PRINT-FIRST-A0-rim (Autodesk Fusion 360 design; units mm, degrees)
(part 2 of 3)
sketch "B Facet 180 Triangle 3" plane through (0, -75, 0) normal (0, -1, 0) x axis (-1, 0, 0)
  line L1 (60.9665, 27.066) -> (-2.067, -27.066)
  line L2 (124, -27.066) -> (60.9665, 27.066)
  line L3 (-2.067, -27.066) -> (124, -27.066)
  line L4 (60.9665, 21.7934) -> (8.7304, -23.066)
  line L5 (113.2026, -23.066) -> (60.9665, 21.7934)
  line L6 (8.7304, -23.066) -> (113.2026, -23.066)
  point P1 (0, 0)
  point P2 (-2.067, -27.066)
  point P3 (60.9665, 27.066)
  point P4 (124, -27.066)
  dimension "d477" distance P1 P2 = 2.067 (= "Linear Dimension-2")
  dimension "d478" distance P1 P2 = 27.066 (= "Linear Dimension-3")
  dimension "d479" distance P1 P3 = 60.9665 (= "Linear Dimension-4")
  dimension "d480" distance P1 P3 = 27.066 (= "Linear Dimension-5")
  dimension "d481" distance P1 P4 = 124 (= "Linear Dimension-6")
  dimension "d482" distance P1 P4 = 27.066 (= "Linear Dimension-7")
  dimension "d483" = 4 (= "memberWidth / 2")
extrude "Extrude14" cut sketch "B Facet 180 Triangle 3" profile of L5 L6 L4 against normal blind 4.7 (magnitude of "-( wall + 0.2 mm )")
sketch "B Facet 180 Triangle 4" plane through (0, -75, 0) normal (0, -1, 0) x axis (-1, 0, 0)
  line L1 (124, -27.066) -> (60.9665, 27.066)
  line L2 (124, 27.066) -> (124, -27.066)
  line L3 (60.9665, 27.066) -> (124, 27.066)
  line L4 (120, -18.3583) -> (71.7639, 23.066)
  line L5 (120, 23.066) -> (120, -18.3583)
  line L6 (71.7639, 23.066) -> (120, 23.066)
  point P1 (0, 0)
  point P2 (60.9665, 27.066)
  point P3 (124, -27.066)
  point P4 (124, 27.066)
  dimension "d486" distance P1 P2 = 60.9665 (= "Linear Dimension-2")
  dimension "d487" distance P1 P2 = 27.066 (= "Linear Dimension-3")
  dimension "d488" distance P1 P3 = 124 (= "Linear Dimension-4")
  dimension "d489" distance P1 P3 = 27.066 (= "Linear Dimension-5")
  dimension "d490" distance P1 P4 = 124 (= "Linear Dimension-6")
  dimension "d491" distance P1 P4 = 27.066 (= "Linear Dimension-7")
  dimension "d492" = -4 (= "-memberWidth / 2")
extrude "Extrude15" cut sketch "B Facet 180 Triangle 4" profile of L5 L6 L4 against normal blind 4.7 (magnitude of "-( wall + 0.2 mm )")
fillet "Fillet5" radius 1.5 (= "apertureRadius")
work_plane "WorkPlane11" RotateAngle 135 ExtraOffset 0
work_plane "WorkPlane12" AlongDistance 75 (= "bodyWidth / 2") ExtraOffset 0
sketch "B Facet 225 Triangle 1" plane through (0, -53.033, -53.033) normal (0, -0.7071, -0.7071) x axis (1, 0, 0)
  line L1 (23.9949, -27.066) -> (62.2721, 27.066)
  line L2 (0.1814, 27.066) -> (23.9949, -27.066)
  line L3 (62.2721, 27.066) -> (0.1814, 27.066)
  line L4 (24.81, -18.9852) -> (54.5447, 23.066)
  line L5 (6.311, 23.066) -> (24.81, -18.9852)
  line L6 (54.5447, 23.066) -> (6.311, 23.066)
  point P1 (0, 0)
  point P2 (62.2721, 27.066)
  point P3 (23.9949, -27.066)
  point P4 (0.1814, 27.066)
  dimension "d501" distance P1 P2 = 62.2721 (= "Linear Dimension-2")
  dimension "d502" distance P1 P2 = 27.066 (= "Linear Dimension-3")
  dimension "d503" distance P1 P3 = 23.9949 (= "Linear Dimension-4")
  dimension "d504" distance P1 P3 = 27.066 (= "Linear Dimension-5")
  dimension "d505" distance P1 P4 = 0.1814 (= "Linear Dimension-6")
  dimension "d506" distance P1 P4 = 27.066 (= "Linear Dimension-7")
  dimension "d507" = 4 (= "memberWidth / 2")
extrude "Extrude16" cut sketch "B Facet 225 Triangle 1" profile of L5 L6 L4 against normal blind 4.7 (magnitude of "-( wall + 0.2 mm )")
sketch "B Facet 225 Triangle 2" plane through (0, -53.033, -53.033) normal (0, -0.7071, -0.7071) x axis (1, 0, 0)
  line L1 (0.1814, 27.066) -> (23.9949, -27.066)
  line L2 (-74.6684, -27.066) -> (0.1814, 27.066)
  line L3 (23.9949, -27.066) -> (-74.6684, -27.066)
  line L4 (-1.4863, 20.9235) -> (17.8653, -23.066)
  line L5 (-62.3117, -23.066) -> (-1.4863, 20.9235)
  line L6 (17.8653, -23.066) -> (-62.3117, -23.066)
  point P1 (0, 0)
  point P2 (23.9949, -27.066)
  point P3 (0.1814, 27.066)
  point P4 (-74.6684, -27.066)
  dimension "d510" distance P1 P2 = 23.9949 (= "Linear Dimension-2")
  dimension "d511" distance P1 P2 = 27.066 (= "Linear Dimension-3")
  dimension "d512" distance P1 P3 = 0.1814 (= "Linear Dimension-4")
  dimension "d513" distance P1 P3 = 27.066 (= "Linear Dimension-5")
  dimension "d514" distance P1 P4 = 74.6684 (= "Linear Dimension-6")
  dimension "d515" distance P1 P4 = 27.066 (= "Linear Dimension-7")
  dimension "d516" = -4 (= "-memberWidth / 2")
extrude "Extrude17" cut sketch "B Facet 225 Triangle 2" profile of L5 L6 L4 against normal blind 4.7 (magnitude of "-( wall + 0.2 mm )")
sketch "B Facet 225 Triangle 3" plane through (0, -53.033, -53.033) normal (0, -0.7071, -0.7071) x axis (1, 0, 0)
  line L1 (-74.6684, -27.066) -> (0.1814, 27.066)
  line L2 (-124, 27.066) -> (-74.6684, -27.066)
  line L3 (0.1814, 27.066) -> (-124, 27.066)
  line L4 (-74.1179, -21.7315) -> (-12.1753, 23.066)
  line L5 (-114.9429, 23.066) -> (-74.1179, -21.7315)
  line L6 (-12.1753, 23.066) -> (-114.9429, 23.066)
  point P1 (0, 0)
  point P2 (0.1814, 27.066)
  point P3 (-74.6684, -27.066)
  point P4 (-124, 27.066)
  dimension "d519" distance P1 P2 = 0.1814 (= "Linear Dimension-2")
  dimension "d520" distance P1 P2 = 27.066 (= "Linear Dimension-3")
  dimension "d521" distance P1 P3 = 74.6684 (= "Linear Dimension-4")
  dimension "d522" distance P1 P3 = 27.066 (= "Linear Dimension-5")
  dimension "d523" distance P1 P4 = 124 (= "Linear Dimension-6")
  dimension "d524" distance P1 P4 = 27.066 (= "Linear Dimension-7")
  dimension "d525" = 4 (= "memberWidth / 2")
extrude "Extrude18" cut sketch "B Facet 225 Triangle 3" profile of L5 L6 L4 against normal blind 4.7 (magnitude of "-( wall + 0.2 mm )")
sketch "B Facet 225 Triangle 4" plane through (0, -53.033, -53.033) normal (0, -0.7071, -0.7071) x axis (1, 0, 0)
  line L1 (-124, 27.066) -> (-74.6684, -27.066)
  line L2 (-124, -27.066) -> (-124, 27.066)
  line L3 (-74.6684, -27.066) -> (-124, -27.066)
  line L4 (-120, 16.7383) -> (-83.7255, -23.066)
  line L5 (-120, -23.066) -> (-120, 16.7383)
  line L6 (-83.7255, -23.066) -> (-120, -23.066)
  point P1 (0, 0)
  point P2 (-74.6684, -27.066)
  point P3 (-124, 27.066)
  point P4 (-124, -27.066)
  dimension "d528" distance P1 P2 = 74.6684 (= "Linear Dimension-2")
  dimension "d529" distance P1 P2 = 27.066 (= "Linear Dimension-3")
  dimension "d530" distance P1 P3 = 124 (= "Linear Dimension-4")
  dimension "d531" distance P1 P3 = 27.066 (= "Linear Dimension-5")
  dimension "d532" distance P1 P4 = 124 (= "Linear Dimension-6")
  dimension "d533" distance P1 P4 = 27.066 (= "Linear Dimension-7")
  dimension "d534" = -4 (= "-memberWidth / 2")
extrude "Extrude19" cut sketch "B Facet 225 Triangle 4" profile of L5 L6 L4 against normal blind 4.7 (magnitude of "-( wall + 0.2 mm )")
fillet "Fillet6" radius 1.5 (= "apertureRadius")
work_plane "WorkPlane13" RotateAngle 180 ExtraOffset 0
work_plane "WorkPlane14" AlongDistance 75 (= "bodyWidth / 2") ExtraOffset 0
sketch "B Facet 270 Triangle 1" plane through (0, 0, -75) normal (0, 0, -1) x axis (-1, 0, 0)
  line L1 (36.9655, 27.066) -> (-17.1665, -27.066)
  line L2 (53.4167, -27.066) -> (36.9655, 27.066)
  line L3 (-17.1665, -27.066) -> (53.4167, -27.066)
  line L4 (35.0777, 19.5214) -> (-7.5097, -23.066)
  line L5 (48.0205, -23.066) -> (35.0777, 19.5214)
  line L6 (-7.5097, -23.066) -> (48.0205, -23.066)
  point P1 (0, 0)
  point P2 (-17.1665, -27.066)
  point P3 (36.9655, 27.066)
  point P4 (53.4167, -27.066)
  dimension "d543" distance P1 P2 = 17.1665 (= "Linear Dimension-2")
  dimension "d544" distance P1 P2 = 27.066 (= "Linear Dimension-3")
  dimension "d545" distance P1 P3 = 36.9655 (= "Linear Dimension-4")
  dimension "d546" distance P1 P3 = 27.066 (= "Linear Dimension-5")
  dimension "d547" distance P1 P4 = 53.4167 (= "Linear Dimension-6")
  dimension "d548" distance P1 P4 = 27.066 (= "Linear Dimension-7")
  dimension "d549" = 4 (= "memberWidth / 2")
extrude "Extrude20" cut sketch "B Facet 270 Triangle 1" profile of L5 L6 L4 against normal blind 4.7 (magnitude of "-( wall + 0.2 mm )")
sketch "B Facet 270 Triangle 2" plane through (0, 0, -75) normal (0, 0, -1) x axis (-1, 0, 0)
  line L1 (53.4167, -27.066) -> (36.9655, 27.066)
  line L2 (124, 27.066) -> (53.4167, -27.066)
  line L3 (36.9655, 27.066) -> (124, 27.066)
  line L4 (55.5648, -20.3777) -> (42.3618, 23.066)
  line L5 (112.2115, 23.066) -> (55.5648, -20.3777)
  line L6 (42.3618, 23.066) -> (112.2115, 23.066)
  point P1 (0, 0)
  point P2 (36.9655, 27.066)
  point P3 (53.4167, -27.066)
  point P4 (124, 27.066)
  dimension "d552" distance P1 P2 = 36.9655 (= "Linear Dimension-2")
  dimension "d553" distance P1 P2 = 27.066 (= "Linear Dimension-3")
  dimension "d554" distance P1 P3 = 53.4167 (= "Linear Dimension-4")
  dimension "d555" distance P1 P3 = 27.066 (= "Linear Dimension-5")
  dimension "d556" distance P1 P4 = 124 (= "Linear Dimension-6")
  dimension "d557" distance P1 P4 = 27.066 (= "Linear Dimension-7")
  dimension "d558" = -4 (= "-memberWidth / 2")
extrude "Extrude21" cut sketch "B Facet 270 Triangle 2" profile of L5 L6 L4 against normal blind 4.7 (magnitude of "-( wall + 0.2 mm )")
sketch "B Facet 270 Triangle 3" plane through (0, 0, -75) normal (0, 0, -1) x axis (-1, 0, 0)
  line L1 (124, 27.066) -> (53.4167, -27.066)
  line L2 (124, -27.066) -> (124, 27.066)
  line L3 (53.4167, -27.066) -> (124, -27.066)
  line L4 (120, 18.9574) -> (65.2053, -23.066)
  line L5 (120, -23.066) -> (120, 18.9574)
  line L6 (65.2053, -23.066) -> (120, -23.066)
  point P1 (0, 0)
  point P2 (53.4167, -27.066)
  point P3 (124, 27.066)
  point P4 (124, -27.066)
  dimension "d561" distance P1 P2 = 53.4167 (= "Linear Dimension-2")
  dimension "d562" distance P1 P2 = 27.066 (= "Linear Dimension-3")
  dimension "d563" distance P1 P3 = 124 (= "Linear Dimension-4")
  dimension "d564" distance P1 P3 = 27.066 (= "Linear Dimension-5")
  dimension "d565" distance P1 P4 = 124 (= "Linear Dimension-6")
  dimension "d566" distance P1 P4 = 27.066 (= "Linear Dimension-7")
  dimension "d567" = 4 (= "memberWidth / 2")
extrude "Extrude22" cut sketch "B Facet 270 Triangle 3" profile of L5 L6 L4 against normal blind 4.7 (magnitude of "-( wall + 0.2 mm )")
fillet "Fillet7" radius 1.5 (= "apertureRadius")
work_plane "WorkPlane15" RotateAngle 225 ExtraOffset 0
work_plane "WorkPlane16" AlongDistance 75 (= "bodyWidth / 2") ExtraOffset 0
sketch "B Facet 315 Triangle 1" plane through (0, 53.033, -53.033) normal (0, 0.7071, -0.7071) x axis (1, 0, 0)
  line L1 (-82.0711, -27.066) -> (-43.7939, 27.066)
  line L2 (-124, 27.066) -> (-82.0711, -27.066)
  line L3 (-43.7939, 27.066) -> (-124, 27.066)
  line L4 (-82.2175, -20.3449) -> (-51.5213, 23.066)
  line L5 (-115.8422, 23.066) -> (-82.2175, -20.3449)
  line L6 (-51.5213, 23.066) -> (-115.8422, 23.066)
  point P1 (0, 0)
  point P2 (-43.7939, 27.066)
  point P3 (-82.0711, -27.066)
  point P4 (-124, 27.066)
  dimension "d576" distance P1 P2 = 43.7939 (= "Linear Dimension-2")
  dimension "d577" distance P1 P2 = 27.066 (= "Linear Dimension-3")
  dimension "d578" distance P1 P3 = 82.0711 (= "Linear Dimension-4")
  dimension "d579" distance P1 P3 = 27.066 (= "Linear Dimension-5")
  dimension "d580" distance P1 P4 = 124 (= "Linear Dimension-6")
  dimension "d581" distance P1 P4 = 27.066 (= "Linear Dimension-7")
  dimension "d582" = 4 (= "memberWidth / 2")
extrude "Extrude23" cut sketch "B Facet 315 Triangle 1" profile of L5 L6 L4 against normal blind 4.7 (magnitude of "-( wall + 0.2 mm )")
sketch "B Facet 315 Triangle 2" plane through (0, 53.033, -53.033) normal (0, 0.7071, -0.7071) x axis (1, 0, 0)
  line L1 (-124, 27.066) -> (-82.0711, -27.066)
  line L2 (-124, -27.066) -> (-124, 27.066)
  line L3 (-82.0711, -27.066) -> (-124, -27.066)
  line L4 (-120, 15.3697) -> (-90.2289, -23.066)
  line L5 (-120, -23.066) -> (-120, 15.3697)
  line L6 (-90.2289, -23.066) -> (-120, -23.066)
  point P1 (0, 0)
  point P2 (-82.0711, -27.066)
  point P3 (-124, 27.066)
  point P4 (-124, -27.066)
  dimension "d585" distance P1 P2 = 82.0711 (= "Linear Dimension-2")
  dimension "d586" distance P1 P2 = 27.066 (= "Linear Dimension-3")
  dimension "d587" distance P1 P3 = 124 (= "Linear Dimension-4")
  dimension "d588" distance P1 P3 = 27.066 (= "Linear Dimension-5")
  dimension "d589" distance P1 P4 = 124 (= "Linear Dimension-6")
  dimension "d590" distance P1 P4 = 27.066 (= "Linear Dimension-7")
  dimension "d591" = -4 (= "-memberWidth / 2")
extrude "Extrude24" cut sketch "B Facet 315 Triangle 2" profile of L5 L6 L4 against normal blind 4.7 (magnitude of "-( wall + 0.2 mm )")
fillet "Fillet8" radius 1.5 (= "apertureRadius")
work_plane "WorkPlane17" AlongDistance 0.5 (= "qFront") ExtraOffset 0
sketch "A Central Carrier sketch" plane through (0.3536, 0.3536, 0) normal (0.7071, 0.7071, 0) x axis (0, 0, 1)
  circle C1 centre (0, 0) radius 26
  dimension "d598" diameter C1 = 52 (= "carrierOD")
extrude "Extrude25" new body sketch "A Central Carrier sketch" along normal blind 18 (= "spokeDepth")
work_plane "WorkPlane18" AlongDistance 0.5 (= "qFront") ExtraOffset 0
sketch "A Spoke 1 Profile" plane through (0.3536, 0.3536, 0) normal (0.7071, 0.7071, 0) x axis (0, 0, 1)
  line L1 (37.3643, -145.3579) -> (-4.7984, -1.4054)
  line L2 (46.9611, -142.547) -> (37.3643, -145.3579)
  line L3 (4.7984, 1.4054) -> (46.9611, -142.547)
  line L4 (-4.7984, -1.4054) -> (4.7984, 1.4054)
  point P1 (0, 0)
  point P2 (-4.7984, -1.4054)
  point P3 (37.3643, -145.3579)
  point P4 (46.9611, -142.547)
  point P5 (4.7984, 1.4054)
  dimension "d603" distance P1 P2 = 4.7984 (= "Linear Dimension-2")
  dimension "d604" distance P1 P2 = 1.4054 (= "Linear Dimension-3")
  dimension "d605" distance P1 P3 = 37.3643 (= "Linear Dimension-4")
  dimension "d606" distance P1 P3 = 145.3579 (= "Linear Dimension-5")
  dimension "d607" distance P1 P4 = 46.9611 (= "Linear Dimension-6")
  dimension "d608" distance P1 P4 = 142.547 (= "Linear Dimension-7")
  dimension "d609" distance P1 P5 = 4.7984 (= "Linear Dimension-8")
  dimension "d610" distance P1 P5 = 1.4054 (= "Linear Dimension-9")
extrude "Extrude26" add sketch "A Spoke 1 Profile" along normal blind 18 (= "spokeDepth")
sketch "A Spoke 2 Profile" plane through (0.3536, 0.3536, 0) normal (0.7071, 0.7071, 0) x axis (0, 0, 1)
  line L1 (126.9012, -80.1317) -> (-2.5272, -4.3143)
  line L2 (131.9557, -71.5031) -> (126.9012, -80.1317)
  line L3 (2.5272, 4.3143) -> (131.9557, -71.5031)
  line L4 (-2.5272, -4.3143) -> (2.5272, 4.3143)
  point P1 (0, 0)
  point P2 (-2.5272, -4.3143)
  point P3 (126.9012, -80.1317)
  point P4 (131.9557, -71.5031)
  point P5 (2.5272, 4.3143)
  dimension "d613" distance P1 P2 = 2.5272 (= "Linear Dimension-2")
  dimension "d614" distance P1 P2 = 4.3143 (= "Linear Dimension-3")
  dimension "d615" distance P1 P3 = 126.9012 (= "Linear Dimension-4")
  dimension "d616" distance P1 P3 = 80.1317 (= "Linear Dimension-5")
  dimension "d617" distance P1 P4 = 131.9557 (= "Linear Dimension-6")
  dimension "d618" distance P1 P4 = 71.5031 (= "Linear Dimension-7")
  dimension "d619" distance P1 P5 = 2.5272 (= "Linear Dimension-8")
  dimension "d620" distance P1 P5 = 4.3143 (= "Linear Dimension-9")
extrude "Extrude27" add sketch "A Spoke 2 Profile" along normal blind 18 (= "spokeDepth")
sketch "A Spoke 3 Profile" plane through (0.3536, 0.3536, 0) normal (0.7071, 0.7071, 0) x axis (0, 0, 1)
  line L1 (131.9557, 71.5031) -> (2.5272, -4.3143)
  line L2 (126.9012, 80.1317) -> (131.9557, 71.5031)
  line L3 (-2.5272, 4.3143) -> (126.9012, 80.1317)
  line L4 (2.5272, -4.3143) -> (-2.5272, 4.3143)
  point P1 (0, 0)
  point P2 (2.5272, -4.3143)
  point P3 (131.9557, 71.5031)
  point P4 (126.9012, 80.1317)
  point P5 (-2.5272, 4.3143)
  dimension "d623" distance P1 P2 = 2.5272 (= "Linear Dimension-2")
  dimension "d624" distance P1 P2 = 4.3143 (= "Linear Dimension-3")
  dimension "d625" distance P1 P3 = 131.9557 (= "Linear Dimension-4")
  dimension "d626" distance P1 P3 = 71.5031 (= "Linear Dimension-5")
  dimension "d627" distance P1 P4 = 126.9012 (= "Linear Dimension-6")
  dimension "d628" distance P1 P4 = 80.1317 (= "Linear Dimension-7")
  dimension "d629" distance P1 P5 = 2.5272 (= "Linear Dimension-8")
  dimension "d630" distance P1 P5 = 4.3143 (= "Linear Dimension-9")
extrude "Extrude28" add sketch "A Spoke 3 Profile" along normal blind 18 (= "spokeDepth")
sketch "A Spoke 4 Profile" plane through (0.3536, 0.3536, 0) normal (0.7071, 0.7071, 0) x axis (0, 0, 1)
  line L1 (46.9611, 142.547) -> (4.7984, -1.4054)
  line L2 (37.3643, 145.3579) -> (46.9611, 142.547)
  line L3 (-4.7984, 1.4054) -> (37.3643, 145.3579)
  line L4 (4.7984, -1.4054) -> (-4.7984, 1.4054)
  point P1 (0, 0)
  point P2 (4.7984, -1.4054)
  point P3 (46.9611, 142.547)
  point P4 (37.3643, 145.3579)
  point P5 (-4.7984, 1.4054)
  dimension "d633" distance P1 P2 = 4.7984 (= "Linear Dimension-2")
  dimension "d634" distance P1 P2 = 1.4054 (= "Linear Dimension-3")
  dimension "d635" distance P1 P3 = 46.9611 (= "Linear Dimension-4")
  dimension "d636" distance P1 P3 = 142.547 (= "Linear Dimension-5")
  dimension "d637" distance P1 P4 = 37.3643 (= "Linear Dimension-6")
  dimension "d638" distance P1 P4 = 145.3579 (= "Linear Dimension-7")
  dimension "d639" distance P1 P5 = 4.7984 (= "Linear Dimension-8")
  dimension "d640" distance P1 P5 = 1.4054 (= "Linear Dimension-9")
extrude "Extrude29" add sketch "A Spoke 4 Profile" along normal blind 18 (= "spokeDepth")
sketch "A Spoke 5 Profile" plane through (0.3536, 0.3536, 0) normal (0.7071, 0.7071, 0) x axis (0, 0, 1)
  line L1 (-37.3643, 145.3579) -> (4.7984, 1.4054)
  line L2 (-46.9611, 142.547) -> (-37.3643, 145.3579)
  line L3 (-4.7984, -1.4054) -> (-46.9611, 142.547)
  line L4 (4.7984, 1.4054) -> (-4.7984, -1.4054)
  point P1 (0, 0)
  point P2 (4.7984, 1.4054)
  point P3 (-37.3643, 145.3579)
  point P4 (-46.9611, 142.547)
  point P5 (-4.7984, -1.4054)
  dimension "d643" distance P1 P2 = 4.7984 (= "Linear Dimension-2")
  dimension "d644" distance P1 P2 = 1.4054 (= "Linear Dimension-3")
  dimension "d645" distance P1 P3 = 37.3643 (= "Linear Dimension-4")
  dimension "d646" distance P1 P3 = 145.3579 (= "Linear Dimension-5")
  dimension "d647" distance P1 P4 = 46.9611 (= "Linear Dimension-6")
  dimension "d648" distance P1 P4 = 142.547 (= "Linear Dimension-7")
  dimension "d649" distance P1 P5 = 4.7984 (= "Linear Dimension-8")
  dimension "d650" distance P1 P5 = 1.4054 (= "Linear Dimension-9")
extrude "Extrude30" add sketch "A Spoke 5 Profile" along normal blind 18 (= "spokeDepth")
sketch "A Spoke 6 Profile" plane through (0.3536, 0.3536, 0) normal (0.7071, 0.7071, 0) x axis (0, 0, 1)
  line L1 (-126.9012, 80.1317) -> (2.5272, 4.3143)
  line L2 (-131.9557, 71.5031) -> (-126.9012, 80.1317)
  line L3 (-2.5272, -4.3143) -> (-131.9557, 71.5031)
  line L4 (2.5272, 4.3143) -> (-2.5272, -4.3143)
  point P1 (0, 0)
  point P2 (2.5272, 4.3143)
  point P3 (-126.9012, 80.1317)
  point P4 (-131.9557, 71.5031)
  point P5 (-2.5272, -4.3143)
  dimension "d653" distance P1 P2 = 2.5272 (= "Linear Dimension-2")
  dimension "d654" distance P1 P2 = 4.3143 (= "Linear Dimension-3")
  dimension "d655" distance P1 P3 = 126.9012 (= "Linear Dimension-4")
  dimension "d656" distance P1 P3 = 80.1317 (= "Linear Dimension-5")
  dimension "d657" distance P1 P4 = 131.9557 (= "Linear Dimension-6")
  dimension "d658" distance P1 P4 = 71.5031 (= "Linear Dimension-7")
  dimension "d659" distance P1 P5 = 2.5272 (= "Linear Dimension-8")
  dimension "d660" distance P1 P5 = 4.3143 (= "Linear Dimension-9")
extrude "Extrude31" add sketch "A Spoke 6 Profile" along normal blind 18 (= "spokeDepth")
sketch "A Spoke 7 Profile" plane through (0.3536, 0.3536, 0) normal (0.7071, 0.7071, 0) x axis (0, 0, 1)
  line L1 (-131.9557, -71.5031) -> (-2.5272, 4.3143)
  line L2 (-126.9012, -80.1317) -> (-131.9557, -71.5031)
  line L3 (2.5272, -4.3143) -> (-126.9012, -80.1317)
  line L4 (-2.5272, 4.3143) -> (2.5272, -4.3143)
  point P1 (0, 0)
  point P2 (-2.5272, 4.3143)
  point P3 (-131.9557, -71.5031)
  point P4 (-126.9012, -80.1317)
  point P5 (2.5272, -4.3143)
  dimension "d663" distance P1 P2 = 2.5272 (= "Linear Dimension-2")
  dimension "d664" distance P1 P2 = 4.3143 (= "Linear Dimension-3")
  dimension "d665" distance P1 P3 = 131.9557 (= "Linear Dimension-4")
  dimension "d666" distance P1 P3 = 71.5031 (= "Linear Dimension-5")
  dimension "d667" distance P1 P4 = 126.9012 (= "Linear Dimension-6")
  dimension "d668" distance P1 P4 = 80.1317 (= "Linear Dimension-7")
  dimension "d669" distance P1 P5 = 2.5272 (= "Linear Dimension-8")
  dimension "d670" distance P1 P5 = 4.3143 (= "Linear Dimension-9")
extrude "Extrude32" add sketch "A Spoke 7 Profile" along normal blind 18 (= "spokeDepth")
sketch "A Spoke 8 Profile" plane through (0.3536, 0.3536, 0) normal (0.7071, 0.7071, 0) x axis (0, 0, 1)
  line L1 (-46.9611, -142.547) -> (-4.7984, 1.4054)
  line L2 (-37.3643, -145.3579) -> (-46.9611, -142.547)
  line L3 (4.7984, 1.4054) -> (-37.3643, -145.3579)
  line L4 (-4.7984, 1.4054) -> (4.7984, 1.4054)
  point P1 (0, 0)
  point P2 (-4.7984, 1.4054)
  point P3 (-46.9611, -142.547)
  point P4 (-37.3643, -145.3579)
  point P5 (4.7984, 1.4054)
  dimension "d673" distance P1 P2 = 4.7984 (= "Linear Dimension-2")
  dimension "d674" distance P1 P2 = 1.4054 (= "Linear Dimension-3")
  dimension "d675" distance P1 P3 = 46.9611 (= "Linear Dimension-4")
  dimension "d676" distance P1 P3 = 142.547 (= "Linear Dimension-5")
  dimension "d677" distance P1 P4 = 37.3643 (= "Linear Dimension-6")
  dimension "d678" distance P1 P4 = 145.3579 (= "Linear Dimension-7")
  dimension "d679" distance P1 P5 = 4.7984 (= "Linear Dimension-8")
  dimension "d680" distance P1 P5 = 1.4054 (= "Linear Dimension-9")
extrude "Extrude33" add sketch "A Spoke 8 Profile" along normal blind 18 (= "spokeDepth")
sketch "Spoke Outer Envelope" plane through (0, 0, 0) normal (1, 0, 0) x axis (0, 0, -1)
  line L1 (31.066, 75) -> (75, 31.066)
  line L2 (-31.066, 75) -> (31.066, 75)
  line L3 (-75, 31.066) -> (-31.066, 75)
  line L4 (-75, -31.066) -> (-75, 31.066)
  line L5 (-31.066, -75) -> (-75, -31.066)
  line L6 (31.066, -75) -> (-31.066, -75)
  line L7 (75, -31.066) -> (31.066, -75)
  line L8 (75, 31.066) -> (75, -31.066)
  point P1 (0, 0)
  point P10 (0, 0)
  point P3 (31.066, 75)
  point P8 (31.066, -75)
  coincident P1 P10
  horizontal L2
  dimension "d683" distance P3 P8 = 150 (= "bodyWidth")
extrude "Extrude34" sketch "Spoke Outer Envelope" distance 260 (= "bodyLength")
fillet "Fillet9" radius 1 (= "rootRadius")
work_plane "WorkPlane19" AlongDistance 10.6 (= "qFrontBack") ExtraOffset 0
sketch "A Rear Carrier Clearance sketch" plane through (7.4953, 7.4953, 0) normal (0.7071, 0.7071, 0) x axis (0, 0, 1)
  circle C1 centre (0, 0) radius 23
  dimension "d690" diameter C1 = 46 (= "rearCarrierClearance")
extrude "Extrude35" cut sketch "A Rear Carrier Clearance sketch" along normal blind 18 (= "spokeDepth")
work_plane "WorkPlane20" AlongDistance 0.5 (= "qFront") ExtraOffset 0
sketch "A Seal Relief sketch" plane through (0.3536, 0.3536, 0) normal (0.7071, 0.7071, 0) x axis (0, 0, 1)
  circle C1 centre (0, 0) radius 9.75
  dimension "d695" diameter C1 = 19.5 (= "raceRelief")
extrude "Extrude36" cut sketch "A Seal Relief sketch" along normal blind 10.1 (= "frontSeatDepth + shoulder")
work_plane "WorkPlane21" AlongDistance 0.5 (= "qFront") ExtraOffset 0
sketch "A Front Bearing Seat sketch" plane through (0.3536, 0.3536, 0) normal (0.7071, 0.7071, 0) x axis (0, 0, 1)
  circle C1 centre (0, 0) radius 11.1
  dimension "d700" diameter C1 = 22.2 (= "seatDiameter")
extrude "Extrude37" cut sketch "A Front Bearing Seat sketch" along normal blind 7.1 (= "frontSeatDepth")
work_plane "WorkPlane22" AlongDistance 0.5 (= "qFront") ExtraOffset 0
sketch "A Support Bolt seed" plane through (0.3536, 0.3536, 0) normal (0.7071, 0.7071, 0) x axis (0, 0, 1)
  line L1 (17, 0) -> (0, 0)
  circle C1 centre (17, 0) radius 1.65
  point P1 (0, 0)
  point P2 (17, 0)
  horizontal L1
  dimension "d705" distance P1 P2 = 17 (= "supportCircle / 2")
  dimension "d706" diameter C1 = 3.3 (= "m3Clearance")
extrude "Extrude38" cut sketch "A Support Bolt seed" profile of C1 along normal blind 10.1 (= "frontSeatDepth + shoulder")
circular_pattern "C-Pattern1" TotalAngle 360
work_plane "WorkPlane23" AlongDistance 0.5 (= "qFront") ExtraOffset 0
sketch "A Front Bearing Boss sketch" plane through (0.3536, 0.3536, 0) normal (0.7071, 0.7071, 0) x axis (0, 0, 1)
  circle C1 centre (0, 0) radius 22
  dimension "d713" diameter C1 = 44 (= "coreOD")
chamfer "Chamfer1" distance 0.4 (= "entryChamfer")
work_plane "WorkPlane24" AlongDistance 75 (= "bodyWidth / 2") ExtraOffset 0
sketch "A Collar Driver Corridors" plane through (0, 0, 75) normal (0, 0, 1) x axis (1, 0, 0)
  circle C1 centre (6.7175, 15.9099) radius 3
  circle C2 centre (15.9099, 6.7175) radius 3
  point P1 (0, 0)
  point P2 (6.7175, 15.9099)
  point P3 (15.9099, 6.7175)
  dimension "d717" distance P1 P2 = 6.7175 (= "abs(( 16 mm + ( -6.5 mm ) ) / sqrt(2))")
  dimension "d718" distance P1 P2 = 15.9099 (= "abs(( 16 mm - ( -6.5 mm ) ) / sqrt(2))")
  dimension "d719" diameter C1 = 6
  dimension "d720" distance P1 P3 = 15.9099 (= "abs(( 16 mm + ( 6.5 mm ) ) / sqrt(2))")
  dimension "d721" distance P1 P3 = 6.7175 (= "abs(( 16 mm - ( 6.5 mm ) ) / sqrt(2))")
  dimension "d722" diameter C2 = 6
extrude "Extrude39" cut sketch "A Collar Driver Corridors" against normal blind 75 (magnitude of "-( bodyWidth / 2 )")
work_plane "WorkPlane17" ExtraOffset 0
sketch "B Central Carrier sketch" plane through (-0.3536, -0.3536, 0) normal (0.7071, 0.7071, 0) x axis (0, 0, 1)
  circle C1 centre (0, 0) radius 38
  dimension "d727" diameter C1 = 76 (= "mountOD")
extrude "Extrude25" new body sketch "B Central Carrier sketch" no distance stored
work_plane "WorkPlane18" ExtraOffset 0
sketch "B Spoke 1 Profile" plane through (-0.3536, -0.3536, 0) normal (0.7071, 0.7071, 0) x axis (0, 0, 1)
  line L1 (37.3643, -145.3579) -> (-4.7984, -1.4054)
  line L2 (46.9611, -142.547) -> (37.3643, -145.3579)
  line L3 (4.7984, 1.4054) -> (46.9611, -142.547)
  line L4 (-4.7984, -1.4054) -> (4.7984, 1.4054)
  point P1 (0, 0)
  point P2 (-4.7984, -1.4054)
  point P3 (37.3643, -145.3579)
  point P4 (46.9611, -142.547)
  point P5 (4.7984, 1.4054)
  dimension "d732" distance P1 P2 = 4.7984 (= "Linear Dimension-2")
  dimension "d733" distance P1 P2 = 1.4054 (= "Linear Dimension-3")
  dimension "d734" distance P1 P3 = 37.3643 (= "Linear Dimension-4")
  dimension "d735" distance P1 P3 = 145.3579 (= "Linear Dimension-5")
  dimension "d736" distance P1 P4 = 46.9611 (= "Linear Dimension-6")
  dimension "d737" distance P1 P4 = 142.547 (= "Linear Dimension-7")
  dimension "d738" distance P1 P5 = 4.7984 (= "Linear Dimension-8")
  dimension "d739" distance P1 P5 = 1.4054 (= "Linear Dimension-9")
extrude "Extrude26" add sketch "B Spoke 1 Profile" no distance stored
sketch "B Spoke 2 Profile" plane through (-0.3536, -0.3536, 0) normal (0.7071, 0.7071, 0) x axis (0, 0, 1)
  line L1 (126.9012, -80.1317) -> (-2.5272, -4.3143)
  line L2 (131.9557, -71.5031) -> (126.9012, -80.1317)
  line L3 (2.5272, 4.3143) -> (131.9557, -71.5031)
  line L4 (-2.5272, -4.3143) -> (2.5272, 4.3143)
  point P1 (0, 0)
  point P2 (-2.5272, -4.3143)
  point P3 (126.9012, -80.1317)
  point P4 (131.9557, -71.5031)
  point P5 (2.5272, 4.3143)
  dimension "d742" distance P1 P2 = 2.5272 (= "Linear Dimension-2")
  dimension "d743" distance P1 P2 = 4.3143 (= "Linear Dimension-3")
  dimension "d744" distance P1 P3 = 126.9012 (= "Linear Dimension-4")
  dimension "d745" distance P1 P3 = 80.1317 (= "Linear Dimension-5")
  dimension "d746" distance P1 P4 = 131.9557 (= "Linear Dimension-6")
  dimension "d747" distance P1 P4 = 71.5031 (= "Linear Dimension-7")
  dimension "d748" distance P1 P5 = 2.5272 (= "Linear Dimension-8")
  dimension "d749" distance P1 P5 = 4.3143 (= "Linear Dimension-9")
extrude "Extrude27" add sketch "B Spoke 2 Profile" no distance stored
sketch "B Spoke 3 Profile" plane through (-0.3536, -0.3536, 0) normal (0.7071, 0.7071, 0) x axis (0, 0, 1)
  line L1 (131.9557, 71.5031) -> (2.5272, -4.3143)
  line L2 (126.9012, 80.1317) -> (131.9557, 71.5031)
  line L3 (-2.5272, 4.3143) -> (126.9012, 80.1317)
  line L4 (2.5272, -4.3143) -> (-2.5272, 4.3143)
  point P1 (0, 0)
  point P2 (2.5272, -4.3143)
  point P3 (131.9557, 71.5031)
  point P4 (126.9012, 80.1317)
  point P5 (-2.5272, 4.3143)
  dimension "d752" distance P1 P2 = 2.5272 (= "Linear Dimension-2")
  dimension "d753" distance P1 P2 = 4.3143 (= "Linear Dimension-3")
  dimension "d754" distance P1 P3 = 131.9557 (= "Linear Dimension-4")
  dimension "d755" distance P1 P3 = 71.5031 (= "Linear Dimension-5")
  dimension "d756" distance P1 P4 = 126.9012 (= "Linear Dimension-6")
  dimension "d757" distance P1 P4 = 80.1317 (= "Linear Dimension-7")
  dimension "d758" distance P1 P5 = 2.5272 (= "Linear Dimension-8")
  dimension "d759" distance P1 P5 = 4.3143 (= "Linear Dimension-9")
extrude "Extrude28" add sketch "B Spoke 3 Profile" no distance stored
sketch "B Spoke 4 Profile" plane through (-0.3536, -0.3536, 0) normal (0.7071, 0.7071, 0) x axis (0, 0, 1)
  line L1 (46.9611, 142.547) -> (4.7984, -1.4054)
  line L2 (37.3643, 145.3579) -> (46.9611, 142.547)
  line L3 (-4.7984, 1.4054) -> (37.3643, 145.3579)
  line L4 (4.7984, -1.4054) -> (-4.7984, 1.4054)
  point P1 (0, 0)
  point P2 (4.7984, -1.4054)
  point P3 (46.9611, 142.547)
  point P4 (37.3643, 145.3579)
  point P5 (-4.7984, 1.4054)
  dimension "d762" distance P1 P2 = 4.7984 (= "Linear Dimension-2")
  dimension "d763" distance P1 P2 = 1.4054 (= "Linear Dimension-3")
  dimension "d764" distance P1 P3 = 46.9611 (= "Linear Dimension-4")
  dimension "d765" distance P1 P3 = 142.547 (= "Linear Dimension-5")
  dimension "d766" distance P1 P4 = 37.3643 (= "Linear Dimension-6")
  dimension "d767" distance P1 P4 = 145.3579 (= "Linear Dimension-7")
  dimension "d768" distance P1 P5 = 4.7984 (= "Linear Dimension-8")
  dimension "d769" distance P1 P5 = 1.4054 (= "Linear Dimension-9")
extrude "Extrude29" add sketch "B Spoke 4 Profile" no distance stored
sketch "B Spoke 5 Profile" plane through (-0.3536, -0.3536, 0) normal (0.7071, 0.7071, 0) x axis (0, 0, 1)
  line L1 (-37.3643, 145.3579) -> (4.7984, 1.4054)
  line L2 (-46.9611, 142.547) -> (-37.3643, 145.3579)
  line L3 (-4.7984, -1.4054) -> (-46.9611, 142.547)
  line L4 (4.7984, 1.4054) -> (-4.7984, -1.4054)
  point P1 (0, 0)
  point P2 (4.7984, 1.4054)
  point P3 (-37.3643, 145.3579)
  point P4 (-46.9611, 142.547)
  point P5 (-4.7984, -1.4054)
  dimension "d772" distance P1 P2 = 4.7984 (= "Linear Dimension-2")
  dimension "d773" distance P1 P2 = 1.4054 (= "Linear Dimension-3")
  dimension "d774" distance P1 P3 = 37.3643 (= "Linear Dimension-4")
  dimension "d775" distance P1 P3 = 145.3579 (= "Linear Dimension-5")
  dimension "d776" distance P1 P4 = 46.9611 (= "Linear Dimension-6")
  dimension "d777" distance P1 P4 = 142.547 (= "Linear Dimension-7")
  dimension "d778" distance P1 P5 = 4.7984 (= "Linear Dimension-8")
  dimension "d779" distance P1 P5 = 1.4054 (= "Linear Dimension-9")
extrude "Extrude30" add sketch "B Spoke 5 Profile" no distance stored
sketch "B Spoke 6 Profile" plane through (-0.3536, -0.3536, 0) normal (0.7071, 0.7071, 0) x axis (0, 0, 1)
  line L1 (-126.9012, 80.1317) -> (2.5272, 4.3143)
  line L2 (-131.9557, 71.5031) -> (-126.9012, 80.1317)
  line L3 (-2.5272, -4.3143) -> (-131.9557, 71.5031)
  line L4 (2.5272, 4.3143) -> (-2.5272, -4.3143)
  point P1 (0, 0)
  point P2 (2.5272, 4.3143)
  point P3 (-126.9012, 80.1317)
  point P4 (-131.9557, 71.5031)
  point P5 (-2.5272, -4.3143)
  dimension "d782" distance P1 P2 = 2.5272 (= "Linear Dimension-2")
  dimension "d783" distance P1 P2 = 4.3143 (= "Linear Dimension-3")
  dimension "d784" distance P1 P3 = 126.9012 (= "Linear Dimension-4")
  dimension "d785" distance P1 P3 = 80.1317 (= "Linear Dimension-5")
  dimension "d786" distance P1 P4 = 131.9557 (= "Linear Dimension-6")
  dimension "d787" distance P1 P4 = 71.5031 (= "Linear Dimension-7")
  dimension "d788" distance P1 P5 = 2.5272 (= "Linear Dimension-8")
  dimension "d789" distance P1 P5 = 4.3143 (= "Linear Dimension-9")
extrude "Extrude31" add sketch "B Spoke 6 Profile" no distance stored
sketch "B Spoke 7 Profile" plane through (-0.3536, -0.3536, 0) normal (0.7071, 0.7071, 0) x axis (0, 0, 1)
  line L1 (-131.9557, -71.5031) -> (-2.5272, 4.3143)
  line L2 (-126.9012, -80.1317) -> (-131.9557, -71.5031)
  line L3 (2.5272, -4.3143) -> (-126.9012, -80.1317)
  line L4 (-2.5272, 4.3143) -> (2.5272, -4.3143)
  point P1 (0, 0)
  point P2 (-2.5272, 4.3143)
  point P3 (-131.9557, -71.5031)
  point P4 (-126.9012, -80.1317)
  point P5 (2.5272, -4.3143)
  dimension "d792" distance P1 P2 = 2.5272 (= "Linear Dimension-2")
  dimension "d793" distance P1 P2 = 4.3143 (= "Linear Dimension-3")
  dimension "d794" distance P1 P3 = 131.9557 (= "Linear Dimension-4")
  dimension "d795" distance P1 P3 = 71.5031 (= "Linear Dimension-5")
  dimension "d796" distance P1 P4 = 126.9012 (= "Linear Dimension-6")
  dimension "d797" distance P1 P4 = 80.1317 (= "Linear Dimension-7")
  dimension "d798" distance P1 P5 = 2.5272 (= "Linear Dimension-8")
  dimension "d799" distance P1 P5 = 4.3143 (= "Linear Dimension-9")
extrude "Extrude32" add sketch "B Spoke 7 Profile" no distance stored
sketch "B Spoke 8 Profile" plane through (-0.3536, -0.3536, 0) normal (0.7071, 0.7071, 0) x axis (0, 0, 1)
  line L1 (-46.9611, -142.547) -> (-4.7984, 1.4054)
  line L2 (-37.3643, -145.3579) -> (-46.9611, -142.547)
  line L3 (4.7984, 1.4054) -> (-37.3643, -145.3579)
  line L4 (-4.7984, 1.4054) -> (4.7984, 1.4054)
  point P1 (0, 0)
  point P2 (-4.7984, 1.4054)
  point P3 (-46.9611, -142.547)
  point P4 (-37.3643, -145.3579)
  point P5 (4.7984, 1.4054)
  dimension "d802" distance P1 P2 = 4.7984 (= "Linear Dimension-2")
  dimension "d803" distance P1 P2 = 1.4054 (= "Linear Dimension-3")
  dimension "d804" distance P1 P3 = 46.9611 (= "Linear Dimension-4")
  dimension "d805" distance P1 P3 = 142.547 (= "Linear Dimension-5")
  dimension "d806" distance P1 P4 = 37.3643 (= "Linear Dimension-6")
  dimension "d807" distance P1 P4 = 145.3579 (= "Linear Dimension-7")
  dimension "d808" distance P1 P5 = 4.7984 (= "Linear Dimension-8")
  dimension "d809" distance P1 P5 = 1.4054 (= "Linear Dimension-9")
extrude "Extrude33" add sketch "B Spoke 8 Profile" no distance stored
sketch "Spoke Outer Envelope" plane through (0, 0, 0) normal (1, 0, 0) x axis (0, 0, -1)
  line L1 (31.066, 75) -> (75, 31.066)
  line L2 (-31.066, 75) -> (31.066, 75)
  line L3 (-75, 31.066) -> (-31.066, 75)
  line L4 (-75, -31.066) -> (-75, 31.066)
  line L5 (-31.066, -75) -> (-75, -31.066)
  line L6 (31.066, -75) -> (-31.066, -75)
  line L7 (75, -31.066) -> (31.066, -75)
  line L8 (75, 31.066) -> (75, -31.066)
  point P1 (0, 0)
  point P10 (0, 0)
  point P3 (31.066, 75)
  point P8 (31.066, -75)
  coincident P1 P10
  horizontal L2
  dimension "d812" distance P3 P8 = 150 (= "bodyWidth")
extrude "Extrude34" sketch "Spoke Outer Envelope" distance 260 (= "bodyLength")
fillet "Fillet9" radius 1 (= "rootRadius")
work_plane "WorkPlane19" ExtraOffset 0
sketch "B Open Hub Cavity sketch" plane through (-0.3536, -0.3536, 0) normal (0.7071, 0.7071, 0) x axis (0, 0, 1)
  circle C1 centre (0, 0) radius 25.15
  dimension "d819" diameter C1 = 50.3 (= "mountOpening")
extrude "Extrude35" cut sketch "B Open Hub Cavity sketch" no distance stored
work_plane "WorkPlane20" ExtraOffset 0
sketch "B Four Mount Holes" plane through (-0.3536, -0.3536, 0) normal (0.7071, 0.7071, 0) x axis (0, 0, 1)
  circle C1 centre (22.6274, 22.6274) radius 2.15
  circle C2 centre (-22.6274, 22.6274) radius 2.15
  circle C3 centre (-22.6274, -22.6274) radius 2.15
  circle C4 centre (22.6274, -22.6274) radius 2.15
  point P1 (0, 0)
  point P2 (22.6274, 22.6274)
  point P3 (-22.6274, 22.6274)
  point P4 (-22.6274, -22.6274)
  point P5 (22.6274, -22.6274)
  dimension "d824" distance P1 P2 = 22.6274 (= "abs(mountCircle / ( 2 * sqrt(2) ))")
  dimension "d825" distance P1 P2 = 22.6274 (= "abs(mountCircle / ( 2 * sqrt(2) ))")
  dimension "d826" diameter C1 = 4.3 (= "m4Clearance")
  dimension "d827" distance P1 P3 = 22.6274 (= "abs(-mountCircle / ( 2 * sqrt(2) ))")
  dimension "d828" distance P1 P3 = 22.6274 (= "abs(mountCircle / ( 2 * sqrt(2) ))")
  dimension "d829" diameter C2 = 4.3 (= "m4Clearance")
  dimension "d830" distance P1 P4 = 22.6274 (= "abs(-mountCircle / ( 2 * sqrt(2) ))")
  dimension "d831" distance P1 P4 = 22.6274 (= "abs(-mountCircle / ( 2 * sqrt(2) ))")
  dimension "d832" diameter C3 = 4.3 (= "m4Clearance")
  dimension "d833" distance P1 P5 = 22.6274 (= "abs(mountCircle / ( 2 * sqrt(2) ))")
  dimension "d834" distance P1 P5 = 22.6274 (= "abs(-mountCircle / ( 2 * sqrt(2) ))")
  dimension "d835" diameter C4 = 4.3 (= "m4Clearance")
extrude "Extrude36" cut sketch "B Four Mount Holes" no distance stored
sketch "B M4 Nut Pocket 1" plane through (-0.3536, -0.3536, 0) normal (0.7071, 0.7071, 0) x axis (0, 0, 1)
  line L1 (24.7059, 26.2274) -> (26.7843, 22.6274)
  line L2 (20.549, 26.2274) -> (24.7059, 26.2274)
  line L3 (18.4705, 22.6274) -> (20.549, 26.2274)
  line L4 (20.549, 19.0274) -> (18.4705, 22.6274)
  line L5 (24.7059, 19.0274) -> (20.549, 19.0274)
  line L6 (26.7843, 22.6274) -> (24.7059, 19.0274)
  circle C1 centre (22.6274, 22.6274) radius 4.1569
  point P3 (26.7843, 22.6274)
  point P4 (24.7059, 26.2274)
  point P5 (20.549, 26.2274)
  point P6 (18.4705, 22.6274)
  point P7 (20.549, 19.0274)
  point P8 (24.7059, 19.0274)
  point P1 (0, 0)
  point P2 (22.6274, 22.6274)
  coincident C1 P3
  coincident C1 P4
  coincident C1 P5
  coincident C1 P6
  coincident C1 P7
  coincident C1 P8
  equal L1 L2
  equal L1 L3
  equal L1 L4
  equal L1 L5
  equal L1 L6
  horizontal L2
  dimension "d838" distance P1 P2 = 22.6274 (= "abs(mountCircle / ( 2 * sqrt(2) ))")
  dimension "d839" distance P1 P2 = 22.6274 (= "abs(mountCircle / ( 2 * sqrt(2) ))")
  dimension "d840" diameter C1 = 8.3138 (= "2 * ( nutAF ) / sqrt(3)")
extrude "Extrude37" cut sketch "B M4 Nut Pocket 1" profile of L1 L2 L3 L4 L5 L6 no distance stored
sketch "B M4 Nut Pocket 2" plane through (-0.3536, -0.3536, 0) normal (0.7071, 0.7071, 0) x axis (0, 0, 1)
  line L1 (-20.549, 26.2274) -> (-18.4705, 22.6274)
  line L2 (-24.7059, 26.2274) -> (-20.549, 26.2274)
  line L3 (-26.7843, 22.6274) -> (-24.7059, 26.2274)
  line L4 (-24.7059, 19.0274) -> (-26.7843, 22.6274)
  line L5 (-20.549, 19.0274) -> (-24.7059, 19.0274)
  line L6 (-18.4705, 22.6274) -> (-20.549, 19.0274)
  circle C1 centre (-22.6274, 22.6274) radius 4.1569
  point P3 (-18.4705, 22.6274)
  point P4 (-20.549, 26.2274)
  point P5 (-24.7059, 26.2274)
  point P6 (-26.7843, 22.6274)
  point P7 (-24.7059, 19.0274)
  point P8 (-20.549, 19.0274)
  point P1 (0, 0)
  point P2 (-22.6274, 22.6274)
  coincident C1 P3
  coincident C1 P4
  coincident C1 P5
  coincident C1 P6
  coincident C1 P7
  coincident C1 P8
  equal L1 L2
  equal L1 L3
  equal L1 L4
  equal L1 L5
  equal L1 L6
  horizontal L2
  dimension "d843" distance P1 P2 = 22.6274 (= "abs(-mountCircle / ( 2 * sqrt(2) ))")
  dimension "d844" distance P1 P2 = 22.6274 (= "abs(mountCircle / ( 2 * sqrt(2) ))")
  dimension "d845" diameter C1 = 8.3138 (= "2 * ( nutAF ) / sqrt(3)")
extrude "Extrude38" cut sketch "B M4 Nut Pocket 2" profile of L1 L2 L3 L4 L5 L6 no distance stored
sketch "B M4 Nut Pocket 3" plane through (-0.3536, -0.3536, 0) normal (0.7071, 0.7071, 0) x axis (0, 0, 1)
  line L1 (-20.549, -19.0274) -> (-18.4705, -22.6274)
  line L2 (-24.7059, -19.0274) -> (-20.549, -19.0274)
  line L3 (-26.7843, -22.6274) -> (-24.7059, -19.0274)
  line L4 (-24.7059, -26.2274) -> (-26.7843, -22.6274)
  line L5 (-20.549, -26.2274) -> (-24.7059, -26.2274)
  line L6 (-18.4705, -22.6274) -> (-20.549, -26.2274)
  circle C1 centre (-22.6274, -22.6274) radius 4.1569
  point P3 (-18.4705, -22.6274)
  point P4 (-20.549, -19.0274)
  point P5 (-24.7059, -19.0274)
  point P6 (-26.7843, -22.6274)
  point P7 (-24.7059, -26.2274)
  point P8 (-20.549, -26.2274)
  point P1 (0, 0)
  point P2 (-22.6274, -22.6274)
  coincident C1 P3
  coincident C1 P4
  coincident C1 P5
  coincident C1 P6
  coincident C1 P7
  coincident C1 P8
  equal L1 L2
  equal L1 L3
  equal L1 L4
  equal L1 L5
  equal L1 L6
  horizontal L2
  dimension "d848" distance P1 P2 = 22.6274 (= "abs(-mountCircle / ( 2 * sqrt(2) ))")
  dimension "d849" distance P1 P2 = 22.6274 (= "abs(-mountCircle / ( 2 * sqrt(2) ))")
  dimension "d850" diameter C1 = 8.3138 (= "2 * ( nutAF ) / sqrt(3)")
extrude "Extrude39" cut sketch "B M4 Nut Pocket 3" profile of L1 L2 L3 L4 L5 L6 no distance stored
sketch "B M4 Nut Pocket 4" plane through (-0.3536, -0.3536, 0) normal (0.7071, 0.7071, 0) x axis (0, 0, 1)
  line L1 (24.7059, -19.0274) -> (26.7843, -22.6274)
  line L2 (20.549, -19.0274) -> (24.7059, -19.0274)
  line L3 (18.4705, -22.6274) -> (20.549, -19.0274)
  line L4 (20.549, -26.2274) -> (18.4705, -22.6274)
  line L5 (24.7059, -26.2274) -> (20.549, -26.2274)
  line L6 (26.7843, -22.6274) -> (24.7059, -26.2274)
  circle C1 centre (22.6274, -22.6274) radius 4.1569
  point P3 (26.7843, -22.6274)
  point P4 (24.7059, -19.0274)
  point P5 (20.549, -19.0274)
  point P6 (18.4705, -22.6274)
  point P7 (20.549, -26.2274)
  point P8 (24.7059, -26.2274)
  point P1 (0, 0)
  point P2 (22.6274, -22.6274)
  coincident C1 P3
  coincident C1 P4
  coincident C1 P5
  coincident C1 P6
  coincident C1 P7
  coincident C1 P8
  equal L1 L2
  equal L1 L3
  equal L1 L4
  equal L1 L5
  equal L1 L6
  horizontal L2
  dimension "d853" distance P1 P2 = 22.6274 (= "abs(mountCircle / ( 2 * sqrt(2) ))")
  dimension "d854" distance P1 P2 = 22.6274 (= "abs(-mountCircle / ( 2 * sqrt(2) ))")
  dimension "d855" diameter C1 = 8.3138 (= "2 * ( nutAF ) / sqrt(3)")
extrude "Extrude40" cut sketch "B M4 Nut Pocket 4" profile of L1 L2 L3 L4 L5 L6 no distance stored
sketch "B Hub Service Slots" plane through (0, 0, 0) normal (0, 0, 1) x axis (1, 0, 0)
  line L1 (-30.4056, -12.0208) -> (-14.8492, 3.5355)
  line L2 (-12.0208, -30.4056) -> (-30.4056, -12.0208)
  line L3 (3.5355, -14.8492) -> (-12.0208, -30.4056)
  line L4 (-14.8492, 3.5355) -> (3.5355, -14.8492)
  point P1 (0, 0)
  point P2 (-14.8492, 3.5355)
  point P3 (-30.4056, -12.0208)
  point P4 (-12.0208, -30.4056)
  point P5 (3.5355, -14.8492)
  dimension "d858" distance P1 P2 = 14.8492 (= "abs(( -8 mm - 13 mm ) / sqrt(2))")
  dimension "d859" distance P1 P2 = 3.5355 (= "abs(( -8 mm + 13 mm ) / sqrt(2))")
  dimension "d860" distance P1 P3 = 30.4056 (= "abs(( -30 mm - 13 mm ) / sqrt(2))")
  dimension "d861" distance P1 P3 = 12.0208 (= "abs(( -30 mm + 13 mm ) / sqrt(2))")
  dimension "d862" distance P1 P4 = 12.0208 (= "abs(( -30 mm + 13 mm ) / sqrt(2))")
  dimension "d863" distance P1 P4 = 30.4056 (= "abs(( -30 mm - 13 mm ) / sqrt(2))")
  dimension "d864" distance P1 P5 = 3.5355 (= "abs(( -8 mm + 13 mm ) / sqrt(2))")
  dimension "d865" distance P1 P5 = 14.8492 (= "abs(( -8 mm - 13 mm ) / sqrt(2))")
extrude "Extrude41" cut sketch "B Hub Service Slots" distance 76 (= "mountOD")
chamfer "Chamfer2" distance 0.3 (= "bedRelief")
chamfer "Chamfer3" distance 0.5 (= "tubeCornerChamfer")
chamfer "Chamfer4" sketch "A Facet 135 Triangle 1" distance 0.3 (= "tubeRimChamfer")
work_plane "WorkPlane25" RotateAngle 0 ExtraOffset 0
work_plane "WorkPlane26" AlongDistance 75 (= "bodyWidth / 2") ExtraOffset 0
sketch "A End Cord Port" plane through (0, 0, 75) normal (0, 0, 1) x axis (1, 0, 0)
  line L1 (125, 0) -> (0, 0)
  circle C1 centre (125, 0) radius 2.25
  point P1 (0, 0)
  point P2 (125, 0)
  horizontal L1
  dimension "d875" distance P1 P2 = 125 (= "abs(( 1 ) * ( ( 1 ) * cordStation ) + ( 0 ) * ( 0 mm ))")
  dimension "d876" diameter C1 = 4.5
extrude "Extrude40" cut sketch "A End Cord Port" profile of C1 no distance stored
chamfer "Chamfer5" distance 0.3 (= "bedRelief")
work_plane "WorkPlane27" RotateAngle 180 ExtraOffset 0
work_plane "WorkPlane28" AlongDistance 75 (= "bodyWidth / 2") ExtraOffset 0
sketch "A End Cord Port (1)" plane through (0, 0, -75) normal (0, 0, -1) x axis (-1, 0, 0)
  line L1 (-125, 0) -> (0, 0)
  circle C1 centre (-125, 0) radius 2.25
  point P1 (0, 0)
  point P2 (-125, 0)
  horizontal L1
  dimension "d884" distance P1 P2 = 125 (= "abs(( -1 ) * ( ( 1 ) * cordStation ) + ( 0 ) * ( 0 mm ))")
  dimension "d885" diameter C1 = 4.5
extrude "Extrude41" cut sketch "A End Cord Port (1)" profile of C1 no distance stored
chamfer "Chamfer6" distance 0.3 (= "bedRelief")
chamfer "Chamfer1" distance 0.3 (= "bedRelief")
chamfer "Chamfer2" distance 0.5 (= "tubeCornerChamfer")
chamfer "Chamfer3" sketch "A Facet 135 Triangle 1" distance 0.3 (= "tubeRimChamfer")
work_plane "WorkPlane21" RotateAngle 0 ExtraOffset 0
work_plane "WorkPlane22" AlongDistance 75 (= "bodyWidth / 2") ExtraOffset 0
sketch "B End Cord Port" plane through (0, 0, 75) normal (0, 0, 1) x axis (1, 0, 0)
  line L1 (-125, 0) -> (0, 0)
  circle C1 centre (-125, 0) radius 2.25
  point P1 (0, 0)
  point P2 (-125, 0)
  horizontal L1
  dimension "d896" distance P1 P2 = 125 (= "abs(( 1 ) * ( ( -1 ) * cordStation ) + ( 0 ) * ( 0 mm ))")
  dimension "d897" diameter C1 = 4.5
extrude "Extrude42" cut sketch "B End Cord Port" profile of C1 no distance stored
chamfer "Chamfer4" distance 0.3 (= "bedRelief")
work_plane "WorkPlane23" RotateAngle 180 ExtraOffset 0
work_plane "WorkPlane24" AlongDistance 75 (= "bodyWidth / 2") ExtraOffset 0
sketch "B End Cord Port (1)" plane through (0, 0, -75) normal (0, 0, -1) x axis (-1, 0, 0)
  line L1 (125, 0) -> (0, 0)
  circle C1 centre (125, 0) radius 2.25
  point P1 (0, 0)
  point P2 (125, 0)
  horizontal L1
  dimension "d905" distance P1 P2 = 125 (= "abs(( -1 ) * ( ( -1 ) * cordStation ) + ( 0 ) * ( 0 mm ))")
  dimension "d906" diameter C1 = 4.5
extrude "Extrude43" cut sketch "B End Cord Port (1)" profile of C1 no distance stored
chamfer "Chamfer5" distance 0.3 (= "bedRelief")
work_plane "WorkPlane1" AlongDistance 22.6 (= "qRearBase") ExtraOffset 0
sketch "D Rear Holder Blank sketch" plane through (15.9806, 15.9806, 0) normal (0.7071, 0.7071, 0) x axis (0, 0, 1)
  circle C1 centre (0, 0) radius 22
  dimension "d912" diameter C1 = 44 (= "coreOD")
extrude "Extrude1" new body sketch "D Rear Holder Blank sketch" along normal blind 10.2 (= "shoulder + rearSeatDepth")
work_plane "WorkPlane2" AlongDistance 22.6 (= "qRearBase") ExtraOffset 0
sketch "D Seal Relief sketch" plane through (15.9806, 15.9806, 0) normal (0.7071, 0.7071, 0) x axis (0, 0, 1)
  circle C1 centre (0, 0) radius 9.75
  dimension "d917" diameter C1 = 19.5 (= "raceRelief")
extrude "Extrude2" cut sketch "D Seal Relief sketch" along normal blind 10.2 (= "shoulder + rearSeatDepth")
work_plane "WorkPlane3" AlongDistance 25.6 (= "qRearBearing") ExtraOffset 0
sketch "D Rear Bearing Seat sketch" plane through (18.1019, 18.1019, 0) normal (0.7071, 0.7071, 0) x axis (0, 0, 1)
  circle C1 centre (0, 0) radius 11.1
  dimension "d922" diameter C1 = 22.2 (= "seatDiameter")
extrude "Extrude3" cut sketch "D Rear Bearing Seat sketch" along normal blind 7.2 (= "rearSeatDepth")
work_plane "WorkPlane4" AlongDistance 22.6 (= "qRearBase") ExtraOffset 0
sketch "D Support Bolt seed" plane through (15.9806, 15.9806, 0) normal (0.7071, 0.7071, 0) x axis (0, 0, 1)
  line L1 (17, 0) -> (0, 0)
  circle C1 centre (17, 0) radius 1.65
  point P1 (0, 0)
  point P2 (17, 0)
  horizontal L1
  dimension "d927" distance P1 P2 = 17 (= "supportCircle / 2")
  dimension "d928" diameter C1 = 3.3 (= "m3Clearance")
extrude "Extrude4" cut sketch "D Support Bolt seed" profile of C1 along normal blind 10.2 (= "shoulder + rearSeatDepth")
circular_pattern "C-Pattern1" TotalAngle 360
chamfer "Chamfer1" distance 0.4 (= "entryChamfer")
chamfer "Chamfer2" distance 0.3 (= "bedRelief")
work_plane "WorkPlane1" AlongDistance -2.5 (= "qFront - capThickness") ExtraOffset 0
sketch "C Front Bearing Cap Ring sketch" plane through (-1.7678, -1.7678, 0) normal (0.7071, 0.7071, 0) x axis (0, 0, 1)
  circle C1 centre (0, 0) radius 22
  circle C2 centre (0, 0) radius 9.75
  dimension "d937" diameter C1 = 44 (= "coreOD")
  dimension "d938" diameter C2 = 19.5 (= "raceRelief")
extrude "Extrude1" new body sketch "C Front Bearing Cap Ring sketch" along normal blind 3 (= "capThickness")
work_plane "WorkPlane2" AlongDistance -2.5 (= "qFront - capThickness") ExtraOffset 0
sketch "C Front Bearing Cap Bolt seed" plane through (-1.7678, -1.7678, 0) normal (0.7071, 0.7071, 0) x axis (0, 0, 1)
  line L1 (17, 0) -> (0, 0)
  circle C1 centre (17, 0) radius 1.65
  point P1 (0, 0)
  point P2 (17, 0)
  horizontal L1
  dimension "d943" distance P1 P2 = 17 (= "supportCircle / 2")
  dimension "d944" diameter C1 = 3.3 (= "m3Clearance")
extrude "Extrude2" cut sketch "C Front Bearing Cap Bolt seed" profile of C1 along normal blind 3 (= "capThickness")
circular_pattern "C-Pattern1" TotalAngle 360
chamfer "Chamfer1" distance 0.3 (= "bedRelief")
work_plane "WorkPlane1" AlongDistance 32.8 (= "qRearEnd") ExtraOffset 0
sketch "E Rear Bearing Cap Ring sketch" plane through (23.1931, 23.1931, 0) normal (0.7071, 0.7071, 0) x axis (0, 0, 1)
  circle C1 centre (0, 0) radius 22
  circle C2 centre (0, 0) radius 9.75
  dimension "d952" diameter C1 = 44 (= "coreOD")
  dimension "d953" diameter C2 = 19.5 (= "raceRelief")
extrude "Extrude1" new body sketch "E Rear Bearing Cap Ring sketch" along normal blind 3 (= "capThickness")
work_plane "WorkPlane2" AlongDistance 32.8 (= "qRearEnd") ExtraOffset 0
sketch "E Rear Bearing Cap Bolt seed" plane through (23.1931, 23.1931, 0) normal (0.7071, 0.7071, 0) x axis (0, 0, 1)
  line L1 (17, 0) -> (0, 0)
  circle C1 centre (17, 0) radius 1.65
  point P1 (0, 0)
  point P2 (17, 0)
  horizontal L1
  dimension "d958" distance P1 P2 = 17 (= "supportCircle / 2")
  dimension "d959" diameter C1 = 3.3 (= "m3Clearance")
